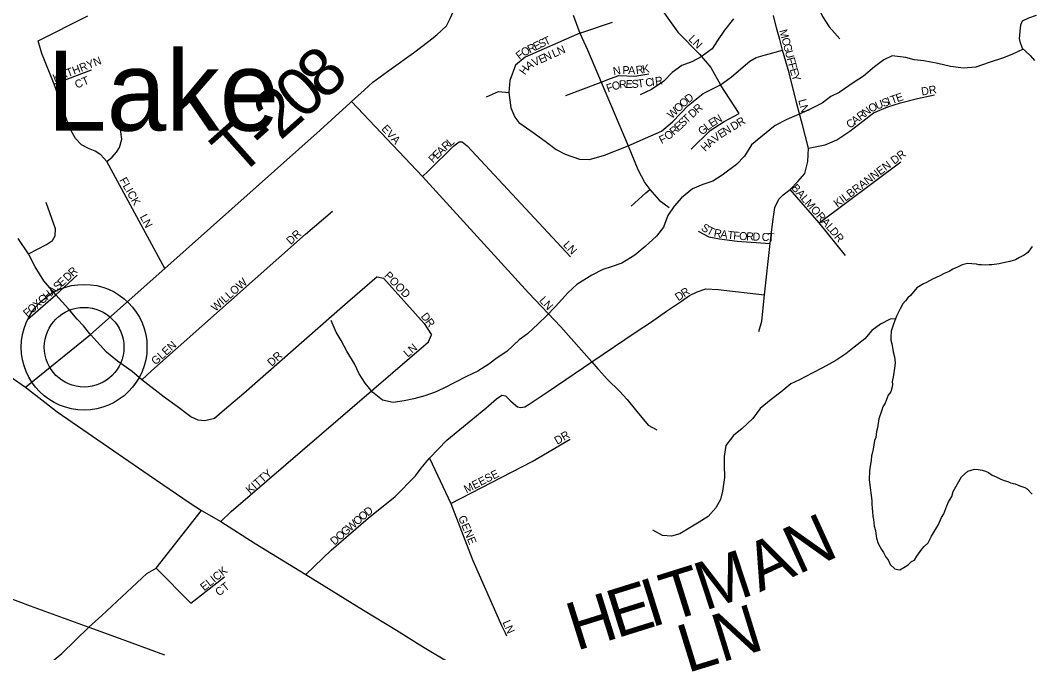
# Model space of a CAD drawing. Extents: x 1310247 to 1664935, y 235267 to 584339.
# Drawn here: x 1471939 to 1478259, y 401910 to 405864 of the extents above; entities that cross this region are included whole.
import ezdxf

# ---------------------------------------------------------------- set-up
doc = ezdxf.new("R2010")
doc.units = 0
for name, color, linetype in [('GM_X_County_Road', 7, 'Continuous'), ('GM_X_Minor_Lake_Text', 7, 'Continuous'), ('GM_X_Minor_River', 7, 'Continuous'), ('GM_X_State_Route', 7, 'Continuous'), ('GM_X_Township_Road', 7, 'Continuous'), ('GM_X_Township_Road_Text', 7, 'Continuous'), ('GM_X_Township_Subdivision', 7, 'Continuous'), ('GM_X_Township_Subdivision_Text', 7, 'Continuous'), ('GM_X_Unincorporated', 7, 'Continuous'), ('GM_X_Unincorporated_Location', 7, 'Continuous')]:
    doc.layers.add(name, color=color, linetype=linetype)

msp = doc.modelspace()

# ---------------------------------------------------------------- linework, layer by layer
at = {"layer": 'GM_X_County_Road'}
for points in [[(1468353.9, 405736.3), (1468697.3, 405538), (1468792.7, 405482.9), (1469292.4, 405229.5), (1469350, 405200), (1469618.3, 405075.7), (1470249.2, 404762.8), (1470613.1, 404555.5), (1470954.4, 404316.9), (1471587.4, 403836.3), (1471896.5, 403622.1), (1471973.2, 403569.9), (1472093.3, 403475.8), (1472170, 403416.6), (1472744.6, 403019.6), (1473001.1, 402845.4), (1473071.6, 402799), (1473192.6, 402730.5), (1473407.1, 402592.7), (1473724.4, 402399.8), (1474083, 402176.5), (1474289.5, 402050.7), (1474453.3, 401948.6), (1474634.7, 401840.6)], [(1472367.3, 402068.8), (1472449.8, 402141.8), (1472730.1, 402405.8), (1472787.6, 402438.8), (1473071.6, 402799)], [(1471883.4, 401687.8), (1471961.8, 401726.5), (1472093.9, 401817.3), (1472198.8, 401904.6), (1472367.3, 402068.8)]]:
    msp.add_lwpolyline(points, dxfattribs=at)
at = {"layer": 'GM_X_Minor_River'}
for points in [[(1476396.4, 405873.8), (1476339, 405802.5), (1476295.6, 405737.1), (1476262.6, 405685.5), (1476193.4, 405634.5), (1476134.6, 405603.4), (1476071.9, 405580.4), (1476012.9, 405537.3), (1475959.8, 405484), (1475882.5, 405431.2), (1475811.6, 405398.3)], [(1478286.6, 405893.7), (1478238.1, 405876.5), (1478199.7, 405859), (1478189.2, 405833.1), (1478184.5, 405795), (1478182.1, 405769), (1478179.8, 405750.9), (1478183.5, 405730.8), (1478198.8, 405690.4), (1478220.6, 405671.9), (1478248.2, 405643.3), (1478275.8, 405612.7)], [(1478205.9, 405684.4), (1478134.1, 405650.7), (1478075.5, 405627.7), (1477992.7, 405601), (1477909.8, 405570.3), (1477833.3, 405563.6), (1477751.2, 405575.1), (1477671.1, 405594.6), (1477585, 405610.1), (1477524.9, 405617.2), (1477472.9, 405632.2), (1477386.7, 405641.7), (1477334.1, 405616.5), (1477277.1, 405573.4), (1477207.7, 405514.4), (1477148.8, 405477.3), (1477055.3, 405412.7), (1477004.6, 405387.5), (1476949.7, 405346.3), (1476878.7, 405309.4), (1476816, 405280.3), (1476728.9, 405243.8), (1476656, 405206.9), (1476566.3, 405134.2), (1476507.2, 405085), (1476463.8, 405013.5), (1476414.7, 404962.2), (1476325.1, 404895.5), (1476266.2, 404858.4), (1476203.6, 404837.4), (1476138.8, 404810.5), (1476071.6, 404753.4), (1476024.5, 404702.1), (1475985.3, 404642.5), (1475957.9, 404570.8), (1475914.7, 404515.3), (1475843.3, 404450.3), (1475780.1, 404395.2), (1475698.8, 404344.5), (1475630.2, 404323.6), (1475579.7, 404306.4), (1475510.7, 404269.5), (1475417.3, 404212.9), (1475362.2, 404161.7), (1475284.3, 404074.8), (1475227.1, 404015.5), (1475176, 403966.2), (1475108.6, 403903.2), (1475055.7, 403866), (1474980.1, 403793), (1474919.2, 403754), (1474866.3, 403714.7), (1474797.2, 403669.8), (1474728.3, 403636.9), (1474655.4, 403600), (1474582.4, 403561.1), (1474531.8, 403540), (1474467.1, 403517), (1474398.5, 403498.1), (1474338, 403485.1), (1474269.5, 403474.3), (1474203.5, 403489.5), (1474140, 403538.8), (1474094.8, 403595.8), (1474057.7, 403654.6), (1474028.6, 403715.3), (1473979.8, 403794.5), (1473944.8, 403861.3), (1473913.6, 403914.1), (1473882.7, 403986.9)], [(1478262.2, 404450.1), (1478233.5, 404412.4), (1478211.1, 404394.8), (1478182.8, 404381.2), (1478156.4, 404365.6), (1478122.1, 404356.1), (1478071.7, 404345), (1478055.6, 404341.2), (1478009.4, 404336), (1477993.3, 404334.3), (1477971.2, 404332.7), (1477945.1, 404335.1), (1477929.1, 404335.4), (1477913.1, 404339.7), (1477885, 404342.2), (1477856.9, 404342.7), (1477824.7, 404335.2), (1477794.3, 404319.7), (1477766, 404308.1), (1477743.7, 404292.5), (1477711.3, 404281), (1477685, 404265.4), (1477638.5, 404246.1), (1477602, 404224.7), (1477581.8, 404217), (1477541.2, 404191.6), (1477502.3, 404144.1), (1477483.9, 404128.3), (1477469.6, 404110.5), (1477453.2, 404090.7), (1477436.6, 404060.9), (1477424.2, 404035), (1477413.8, 404013.1), (1477407.5, 403997.1), (1477394.8, 403963.2), (1477380.1, 403921.3), (1477377.4, 403883.2), (1477379.1, 403865), (1477384.7, 403840.9), (1477388.4, 403818.7), (1477393.9, 403790.5), (1477401.5, 403760.2), (1477404.8, 403722), (1477402.5, 403704), (1477393.3, 403633.8), (1477386.8, 403605.8), (1477388.5, 403587.7), (1477386.2, 403571.7), (1477377.7, 403541.7), (1477361.3, 403519.9), (1477342.4, 403470), (1477327.9, 403448.2), (1477321.5, 403426.2), (1477302.6, 403372.3), (1477295.6, 403316.2), (1477289.2, 403292.2), (1477284.5, 403256.2), (1477276.2, 403236.2), (1477267.2, 403182.2), (1477260.8, 403156.2), (1477258.5, 403140.1), (1477256, 403112.1), (1477249.4, 403076), (1477244.9, 403048), (1477244, 402993.8), (1477249.1, 402941.5), (1477256.4, 402895.2), (1477259.8, 402859)], [(1477407.4, 403996.8), (1477374.1, 403996), (1477313.3, 403965), (1477260.3, 403923.8), (1477215.2, 403872.4), (1477150.1, 403821.3), (1477097.1, 403778.1), (1477034.1, 403737), (1476950.9, 403690.3), (1476886.1, 403657.3), (1476807, 403616.6), (1476754.3, 403591.4), (1476691.1, 403538.3), (1476630.1, 403493.2), (1476562.8, 403436.2), (1476515.5, 403374.8), (1476450.2, 403311.7), (1476395.2, 403268.5), (1476347.9, 403205.1), (1476336.6, 403137.1), (1476337.7, 403082.9), (1476338.3, 403004.6), (1476326.8, 402920.5), (1476313.9, 402868.5), (1476284.8, 402814.8), (1476237.7, 402761.5), (1476180.8, 402726.3), (1476128, 402695.1), (1476061, 402654.1), (1476008.6, 402639), (1475952.4, 402642), (1475890.7, 402677.2)], [(1477259.8, 402859), (1477259.4, 402838.9), (1477261, 402812.8), (1477264.6, 402790.6), (1477266.2, 402762.5), (1477269.9, 402742.3), (1477275.2, 402702), (1477282.8, 402673.8), (1477284.5, 402655.7), (1477288, 402625.5), (1477299.5, 402593.2), (1477309.2, 402574.9), (1477320.9, 402554.6), (1477332.6, 402536.3), (1477346.2, 402508), (1477362, 402491.6), (1477373.5, 402461.3), (1477403.2, 402434.7), (1477419.2, 402430.4), (1477435.2, 402428.1), (1477459.5, 402441.8), (1477485.9, 402459.4), (1477508.3, 402481.1), (1477526.5, 402488.8), (1477541, 402514.6), (1477571.9, 402558.3), (1477586.2, 402574.1), (1477610.7, 402597.8), (1477631.5, 402639.6), (1477664.4, 402691.2), (1477674.7, 402707.1), (1477695.6, 402754.9), (1477710.1, 402778.8), (1477729, 402828.7), (1477739.4, 402852.6), (1477760.1, 402886.3), (1477768.6, 402918.3), (1477820.4, 403009.8), (1477859.1, 403045.3), (1477901.5, 403058.6), (1477923.5, 403056.2), (1477949.6, 403051.7), (1477969.5, 403045.4), (1477989.4, 403037), (1478011.2, 403020.5), (1478037.2, 403010), (1478065, 402995.5), (1478087, 402987.1), (1478108.9, 402980.7), (1478126.9, 402972.3), (1478154.9, 402965.8), (1478184.8, 402953.2), (1478214.7, 402942.7), (1478230.6, 402934.3), (1478262.2, 402901.7)]]:
    msp.add_lwpolyline(points, dxfattribs=at)
at = {"layer": 'GM_X_State_Route'}
msp.add_lwpolyline([(1469060.5, 403282.5), (1469114.2, 403264.6), (1469388.3, 403162.4), (1469576, 403085.4), (1469787.3, 403014.1), (1470030.2, 402928.8), (1470311.2, 402823.7), (1470749.5, 402666.5), (1471027.7, 402562.3), (1471171.1, 402511.9), (1471449.1, 402410.4), (1471691.6, 402320.6), (1472001.2, 402202.4), (1472367.3, 402068.8), (1472535.1, 402009.5), (1472841.4, 401896.1)], dxfattribs=at)
at = {"layer": 'GM_X_Township_Road'}
for points in [[(1474001.2, 405348.9), (1474008.6, 405355.7), (1474087.4, 405426.5), (1474143.2, 405476.4), (1474257.7, 405560.6), (1474396.4, 405661.3), (1474492.3, 405732.9), (1474542.3, 405773.9), (1474601.5, 405828.6), (1474624.4, 405874.5), (1474792.2, 406243.1), (1475185.1, 407181.4), (1475305.4, 407460.8), (1475558.2, 408066.7), (1475552.2, 408102.9), (1475537.1, 408139.9), (1475512.2, 408179.2), (1475454.8, 408244.9), (1475239.9, 408484.7)], [(1471973.2, 403569.9), (1472378.6, 403898.9), (1472842, 404311.7), (1473813.6, 405177.2), (1474001.2, 405348.9)]]:
    msp.add_lwpolyline(points, dxfattribs=at)
at = {"layer": 'GM_X_Township_Subdivision'}
for points in [[(1475348.7, 406688.8), (1475402.8, 406660.7), (1475432.6, 406622.7), (1475673.2, 406291.3), (1475818.3, 406111.8), (1476048.3, 405789.8), (1476182.4, 405651.7), (1476253.5, 405568.7), (1476314.4, 405461.3)], [(1476909.3, 405991.3), (1476924.7, 405947), (1476950.5, 405887.7), (1476993.4, 405822.4), (1477060.8, 405748.9)], [(1472060.1, 405705.4), (1472050.6, 405736.3), (1472362.5, 405891.2)], [(1475394.5, 405895.8), (1475435.3, 405784), (1475482.6, 405680.1), (1475569.5, 405477.6), (1475738.2, 405078.2), (1475798.8, 404930.1), (1475841.3, 404847.2), (1475872.4, 404805.7), (1475931.5, 404740.4), (1475992.7, 404693.7)], [(1475435.3, 405784), (1475639.2, 405852.4)], [(1476553.3, 403917.7), (1476572.2, 403982.9), (1476589.9, 404147.4), (1476625.6, 404467.7), (1476642, 404607), (1476654.7, 404693.8), (1476679.6, 404744.9), (1476706.8, 404771.9), (1476748.5, 404807), (1476797.6, 404856.7), (1476841, 404905.5), (1476859.1, 404981.5), (1476864.5, 405064.7), (1476826.5, 405209.5), (1476790.3, 405341.6), (1476743.3, 405535.1), (1476701.1, 405678), (1476685.8, 405743), (1476664.4, 405817.4), (1476646.1, 405893.8)], [(1475435.3, 405784), (1475211.7, 405685.4), (1475094.7, 405632.8), (1475032.8, 405584.1), (1474998.7, 405488.1), (1474992.1, 405411.8), (1475003.9, 405317.1), (1475030.2, 405257.9), (1475055.2, 405225.1), (1475149.9, 405158), (1475226.2, 405102.8), (1475286.7, 405056.7), (1475343.2, 405027.8), (1475432.7, 404994.9), (1475495.8, 404993.6), (1475590.5, 405021.2), (1475738.2, 405078.2)], [(1472842, 404311.7), (1472480.5, 404981.9), (1472442.8, 405023.1), (1472407.8, 405045), (1472366.6, 405063.4), (1472321.9, 405084.4), (1472285.4, 405124), (1472244.8, 405196.6), (1472207.6, 405308.1), (1472150.5, 405465.1), (1472075, 405656.8), (1472060.1, 405705.4)], [(1475738.2, 405078.2), (1475846.3, 405126.8), (1475945.5, 405170.4), (1476013.8, 405228.7), (1476113.2, 405332.2), (1476205.5, 405405.6), (1476314.4, 405461.3), (1476384, 405509.6), (1476496.8, 405608.9), (1476536.9, 405631.8), (1476595, 405648.2), (1476701.1, 405678)], [(1472150.5, 405465.1), (1472192.7, 405482.2), (1472385, 405554.5)], [(1475569.5, 405477.6), (1475627.3, 405499.9), (1475680, 405518.4), (1475778.6, 405514.4), (1475866.7, 405530.2)], [(1475348.5, 405393.4), (1475569.5, 405477.6)], [(1474852.7, 405385.5), (1474926.3, 405419.7), (1474992.1, 405411.8)], [(1476131, 405058.9), (1476249.1, 405175.4), (1476337.7, 405230.6), (1476430.9, 405281.1), (1476314.4, 405461.3)], [(1474008.6, 405355.7), (1474451.5, 404888.2), (1475115.4, 404160.8), (1475317.4, 403946.8), (1475510.6, 403729.1), (1475548.7, 403684.2), (1475551.1, 403681.6)], [(1476864.5, 405064.7), (1476967.6, 405084.7), (1477041.8, 405117.2), (1477121.5, 405171.5), (1477202.9, 405233), (1477269.8, 405285.5), (1477360.3, 405323.5), (1477438.1, 405348.8), (1477544.8, 405375.9), (1477651.5, 405397.6)], [(1472480.5, 404981.9), (1472513.8, 405007.3), (1472541.8, 405039.7), (1472558.5, 405067.8), (1472574.3, 405120.3), (1472566.3, 405181.4), (1472551.5, 405229.9), (1472523.4, 405292.1)], [(1474451.5, 404888.2), (1474487.7, 404920.9), (1474648.7, 405078.6), (1474681.9, 405104.9), (1474700.9, 405103.5), (1474731.2, 405080), (1475377.9, 404384.1)], [(1476931.5, 404598), (1477439.9, 404979.7)], [(1475755.2, 404702), (1475848.5, 404785), (1475872.4, 404805.7)], [(1477096.1, 404393.5), (1476931.5, 404598), (1476748.5, 404807)], [(1471991.2, 404404.6), (1472104.3, 404462.7), (1472140.6, 404487.9), (1472157.6, 404517.2), (1472159.4, 404559.9), (1472100.8, 404723.9)], [(1472698.3, 403617.1), (1472758.9, 403673.1), (1473721.5, 404526.2), (1473890.5, 404670.7)], [(1476175.2, 404545.5), (1476240.4, 404509.3), (1476307.3, 404496.6), (1476417.7, 404484), (1476625.6, 404467.7)], [(1472374.5, 403904), (1472334.5, 403953.8), (1472295.8, 403995.9), (1472241.6, 404059.8), (1472162.5, 404148.1), (1472086.2, 404235.3), (1472031.9, 404322.9), (1471991.2, 404404.6), (1471927, 404500.7)], [(1471984.3, 403992.4), (1472162.5, 404148.1), (1472294.4, 404270.4)], [(1474170.2, 404259.3), (1473952.3, 404072.8), (1473336.9, 403529.7), (1473214.6, 403428.3), (1473154, 403373.5), (1473093.3, 403359.6), (1473051.4, 403363.1), (1473005.9, 403384), (1472919.7, 403449.3), (1472839.3, 403508.7), (1472698.3, 403617.1), (1472638.9, 403667.2), (1472547.6, 403732.4), (1472477.4, 403788.6), (1472378.6, 403898.9), (1472374.5, 403904)], [(1474170.2, 404259.3), (1474208.7, 404251.1), (1474463.9, 403969.1), (1474508.2, 403896.8)], [(1473724.4, 402399.8), (1473882.5, 402551.4), (1474113.6, 402750.9), (1474281.9, 402886.5), (1474409.7, 403016.5), (1474444.5, 403064), (1474496.1, 403127.3), (1474605, 403239.9), (1474849.2, 403439.9), (1474914.2, 403496.9), (1474948.1, 403520.8), (1474970.1, 403516.4), (1475004, 403483.2), (1475046, 403448.1), (1475066.4, 403442.6), (1475092.8, 403446.5), (1475119.8, 403464.6), (1475236.9, 403543.9), (1475510.6, 403729.1), (1475787.7, 403915.8), (1475876.6, 403975.1), (1475976.4, 404044.6), (1476071.6, 404108.4), (1476120, 404143.6), (1476169.5, 404165.4), (1476223.2, 404185), (1476299.9, 404181.5), (1476589.9, 404147.4)], [(1473192.6, 402730.5), (1473257.5, 402792.3), (1474490.5, 403852.8), (1474508.2, 403896.8)], [(1475551.1, 403681.6), (1475609.2, 403618.8), (1475683.4, 403544.6), (1475732.2, 403493.9), (1475783.9, 403428.5), (1475863, 403332.8), (1475916.7, 403303.5)], [(1474629.3, 402843.4), (1475137.4, 403106.3), (1475375.9, 403244.5)], [(1474496.1, 403127.3), (1474629.3, 402843.4), (1474763.6, 402497)], [(1474763.6, 402497), (1474768, 402485.7), (1474948.8, 402075), (1474969.4, 402034.6), (1474978, 402015.7)], [(1472787.6, 402438.8), (1473004.7, 402220.4), (1473215.5, 402384.3)]]:
    msp.add_lwpolyline(points, dxfattribs=at)
at = {"layer": 'GM_X_Unincorporated'}
for radius in [392.8, 249]:
    msp.add_circle((1472338.5, 403820.1), radius, dxfattribs=at)
at = {"layer": 'GM_X_Unincorporated_Location'}
msp.add_line((1472338.5, 403820.1), (1472338.5, 403820.1), dxfattribs=at)

# ---------------------------------------------------------------- texts
at = {"layer": 'GM_X_Minor_Lake_Text'}
msp.add_text('Lake', height=499.99, rotation=0.00015, dxfattribs=at).set_placement((1472107.6, 405173.5))
at = {"layer": 'GM_X_Township_Road_Text'}
for s, rotation, p in [('8', 42.29734, (1473839.2, 405355.9)), ('0', 42.18811, (1473702.9, 405232.3)), ('2', 41.7779, (1473564.4, 405108.6)), ('T', 41.69466, (1473305.6, 404878.1)), ('-', 41.69801, (1473472.9, 405027.1)), ('N', 24.51359, (1476798.8, 402397.3)), ('A', 24.70994, (1476559.2, 402287.1)), ('M', 18.22652, (1476215.5, 402171.7)), ('T', 17.38189, (1475996.7, 402103.2)), ('I', 17.38356, (1475879.2, 402066.4)), ('E', 17.38189, (1475665, 401999.3)), ('H', 17.38314, (1475413.1, 401920.5)), ('LN', 17.14287, (1476106.9, 401782.3))]:
    msp.add_text(s, height=300, rotation=rotation, dxfattribs=at).set_placement(p)
at = {"layer": 'GM_X_Township_Subdivision_Text'}
for s, rotation, p in [('M', 284.94199, (1476680.9, 405799.8)), ('E', 25.37995, (1475158.3, 405674.3)), ('S', 25.39766, (1475190.1, 405689.4)), ('T', 25.39766, (1475221.9, 405704.5)), ('LN', 315, (1476110.9, 405742.5)), ('C', 284.96382, (1476694.6, 405748.8)), ('F', 38.0068, (1475059.2, 405615)), ('O', 30.20295, (1475085.5, 405635.6)), ('R', 25.5552, (1475122.6, 405657.3)), ('N', 24.14004, (1475222.1, 405607)), ('L', 24.14647, (1475274.4, 405630.4)), ('N', 24.11116, (1475306.5, 405644.8)), ('G', 284.94269, (1476704.8, 405710.6)), ('U', 284.96626, (1476716.1, 405668)), ('KATHRYN', 21.33955, (1472154.3, 405476.3)), ('A', 31.93821, (1475114.6, 405551.1)), ('V', 25.48025, (1475150.6, 405573.7)), ('E', 24.30374, (1475190.1, 405592.5)), ('F', 284.95078, (1476727.5, 405625.5)), ('F', 284.92438, (1476736.6, 405591.5)), ('H', 54.3937, (1475092.7, 405518.9)), ('N', 10.23839, (1475647.2, 405520.2)), ('P', 359.18037, (1475701.1, 405527.8)), ('A', 359.79028, (1475736.9, 405527.2)), ('R', 7.65183, (1475788.4, 405527.6)), ('K', 8.75383, (1475828.7, 405533)), ('E', 286.46894, (1476746, 405556.1)), ('Y', 288.26341, (1476756.5, 405520.7)), ('CT', 22.37755, (1472292.2, 405436.2)), ('F', 19.85236, (1475611.2, 405413)), ('O', 16.67202, (1475643.6, 405424.7)), ('R', 6.42331, (1475683.4, 405436.9)), ('E', 358.96185, (1475721.1, 405441.2)), ('S', 2.80363, (1475759.9, 405440.6)), ('T', 6.5844, (1475798.7, 405442.7)), ('C', 8.13174, (1475848.2, 405448.7)), ('I', 8.298, (1475887.5, 405454.3)), ('R', 8.33352, (1475909.3, 405457.5)), ('D', 39.10022, (1476114.8, 405344.1)), ('E', 18.40039, (1477419.1, 405351.8)), ('DR', 9.46823, (1477572.3, 405393.1)), ('O', 43.60885, (1476051.1, 405284.9)), ('O', 42.15457, (1476082.7, 405315)), ('R', 41.16765, (1476171.9, 405279.7)), ('LN', 284.73508, (1476799.7, 405364.2)), ('O', 26.78011, (1477253.6, 405285.5)), ('U', 20.47419, (1477291.6, 405304.7)), ('S', 20.19787, (1477332.7, 405320.1)), ('I', 20.17735, (1477365.8, 405332.2)), ('T', 20.13716, (1477386.4, 405339.8)), ('W', 43.62079, (1476009.7, 405245.4)), ('T', 43.26078, (1476104.4, 405217.3)), ('D', 42.29427, (1476139.6, 405250.2)), ('N', 30.95733, (1476289, 405211.7)), ('R', 37.85581, (1477189.6, 405235.7)), ('N', 37.4993, (1477220.8, 405260)), ('E', 43.46447, (1476053.3, 405168.9)), ('S', 43.4153, (1476078.9, 405193.1)), ('L', 37.97866, (1476233.2, 405171.6)), ('E', 33.29777, (1476260, 405192.7)), ('D', 30.27327, (1476394.7, 405173)), ('R', 32.87973, (1476434.8, 405196.5)), ('C', 37.85581, (1477123.6, 405184.4)), ('A', 37.85773, (1477154.9, 405208.7)), ('EVA', 312.13924, (1474192.8, 405183.3)), ('F', 27.11478, (1475946, 405089.4)), ('O', 39.08824, (1475986.9, 405111.6)), ('R', 42.58549, (1476023.6, 405141.6)), ('G', 42.65955, (1476201.6, 405142.5)), ('V', 37.1847, (1476282.4, 405098.6)), ('E', 33.44761, (1476316.8, 405124.7)), ('N', 30.93752, (1476345.7, 405143.8)), ('R', 43.77854, (1474600.8, 405047.2)), ('L', 40.92126, (1474628.9, 405074.2)), ('H', 44.79907, (1476220, 405039.2)), ('A', 42.23252, (1476250.7, 405069.8)), ('P', 43.78276, (1474518.2, 404968)), ('E', 43.80267, (1474543.6, 404992.4)), ('A', 43.79427, (1474569, 405016.8)), ('KILBRANNEN DR', 37.0718, (1477044.7, 404691.6)), ('FLICK', 299.74556, (1472557.2, 404864.9)), ('BALMORAL', 311.38906, (1476753.7, 404813.6)), ('LN', 297.89137, (1472684.9, 404635.8)), ('S', 327.20404, (1476189.1, 404555.3)), ('DR', 42.8801, (1473629.4, 404457.9)), ('T', 332.61623, (1476223.2, 404533.7)), ('R', 349.14897, (1476269.3, 404512.3)), ('A', 352.59861, (1476311.4, 404504.3)), ('T', 353.30411, (1476355.7, 404498.6)), ('F', 354.80677, (1476392.1, 404494.3)), ('O', 357.44828, (1476429.7, 404491)), ('R', 357.79622, (1476474, 404489)), ('D', 357.80852, (1476513.6, 404487.5)), ('C', 357.78994, (1476570.7, 404485.3)), ('T', 357.80601, (1476610.3, 404483.8)), ('DR', 308.66337, (1476991.6, 404544.9)), ('LN', 312.88011, (1475327.8, 404457.3)), ('D', 43.16036, (1472235, 404228.9)), ('R', 43.14463, (1472267.1, 404259)), ('POOD', 313.92234, (1474209.9, 404264.2)), ('S', 43.10869, (1472173.9, 404171.7)), ('E', 43.14387, (1472199.6, 404195.7)), ('WILLOW', 41.42564, (1473158.8, 404040.1)), ('C', 41.08081, (1472076.9, 404085.9)), ('H', 41.09762, (1472106.8, 404111.9)), ('A', 42.18079, (1472140.7, 404141.5)), ('LN', 312.87172, (1475178.3, 404109.8)), ('D', 33.50215, (1476050.6, 404106.8)), ('R', 32.71333, (1476087.1, 404131)), ('O', 41.09762, (1472010.6, 404028)), ('X', 41.09762, (1472043.7, 404057)), ('F', 41.07541, (1471984, 404004.9)), ('D', 307.63922, (1474439.6, 404012.4)), ('R', 306.15593, (1474466.3, 403977.8)), ('GLEN', 41.76216, (1472784.8, 403705.6)), ('LN', 40.60386, (1474360.2, 403754)), ('DR', 42.8801, (1473510.6, 403696.7)), ('DR', 30.46386, (1475294.3, 403209.5)), ('KITTY', 41.18447, (1473374.6, 402900.4)), ('MEESE', 27.12099, (1474727.1, 402906.2)), ('D', 38.38676, (1474111.2, 402760.7)), ('O', 41.08724, (1474045, 402703.6)), ('O', 40.51358, (1474078.1, 402732.5)), ('GENE', 292.37982, (1474674.1, 402756.2)), ('G', 41.07076, (1473968.8, 402637.1)), ('W', 41.08486, (1474001.9, 402666)), ('D', 41.08724, (1473902.4, 402579.3)), ('O', 41.08171, (1473935.6, 402608.2)), ('ELICK', 39.09694, (1473088.7, 402293.5)), ('CT', 38.16136, (1473181.6, 402261.2)), ('L', 293.37438, (1474951.3, 402100.7)), ('N', 294.22277, (1474965.6, 402067.6))]:
    msp.add_text(s, height=50, rotation=rotation, dxfattribs=at).set_placement(p)

doc.saveas('drawing.dxf')
